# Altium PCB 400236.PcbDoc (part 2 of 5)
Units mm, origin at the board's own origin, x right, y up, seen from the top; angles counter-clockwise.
Board outline 136.53 x 63.5 mm, 4 copper layers (Top Layer, Mid-Layer 1, Mid-Layer 2, Bottom Layer), stack 1.505 mm thick; 340 components, 230 nets, 1369 pads, 1292 vias.
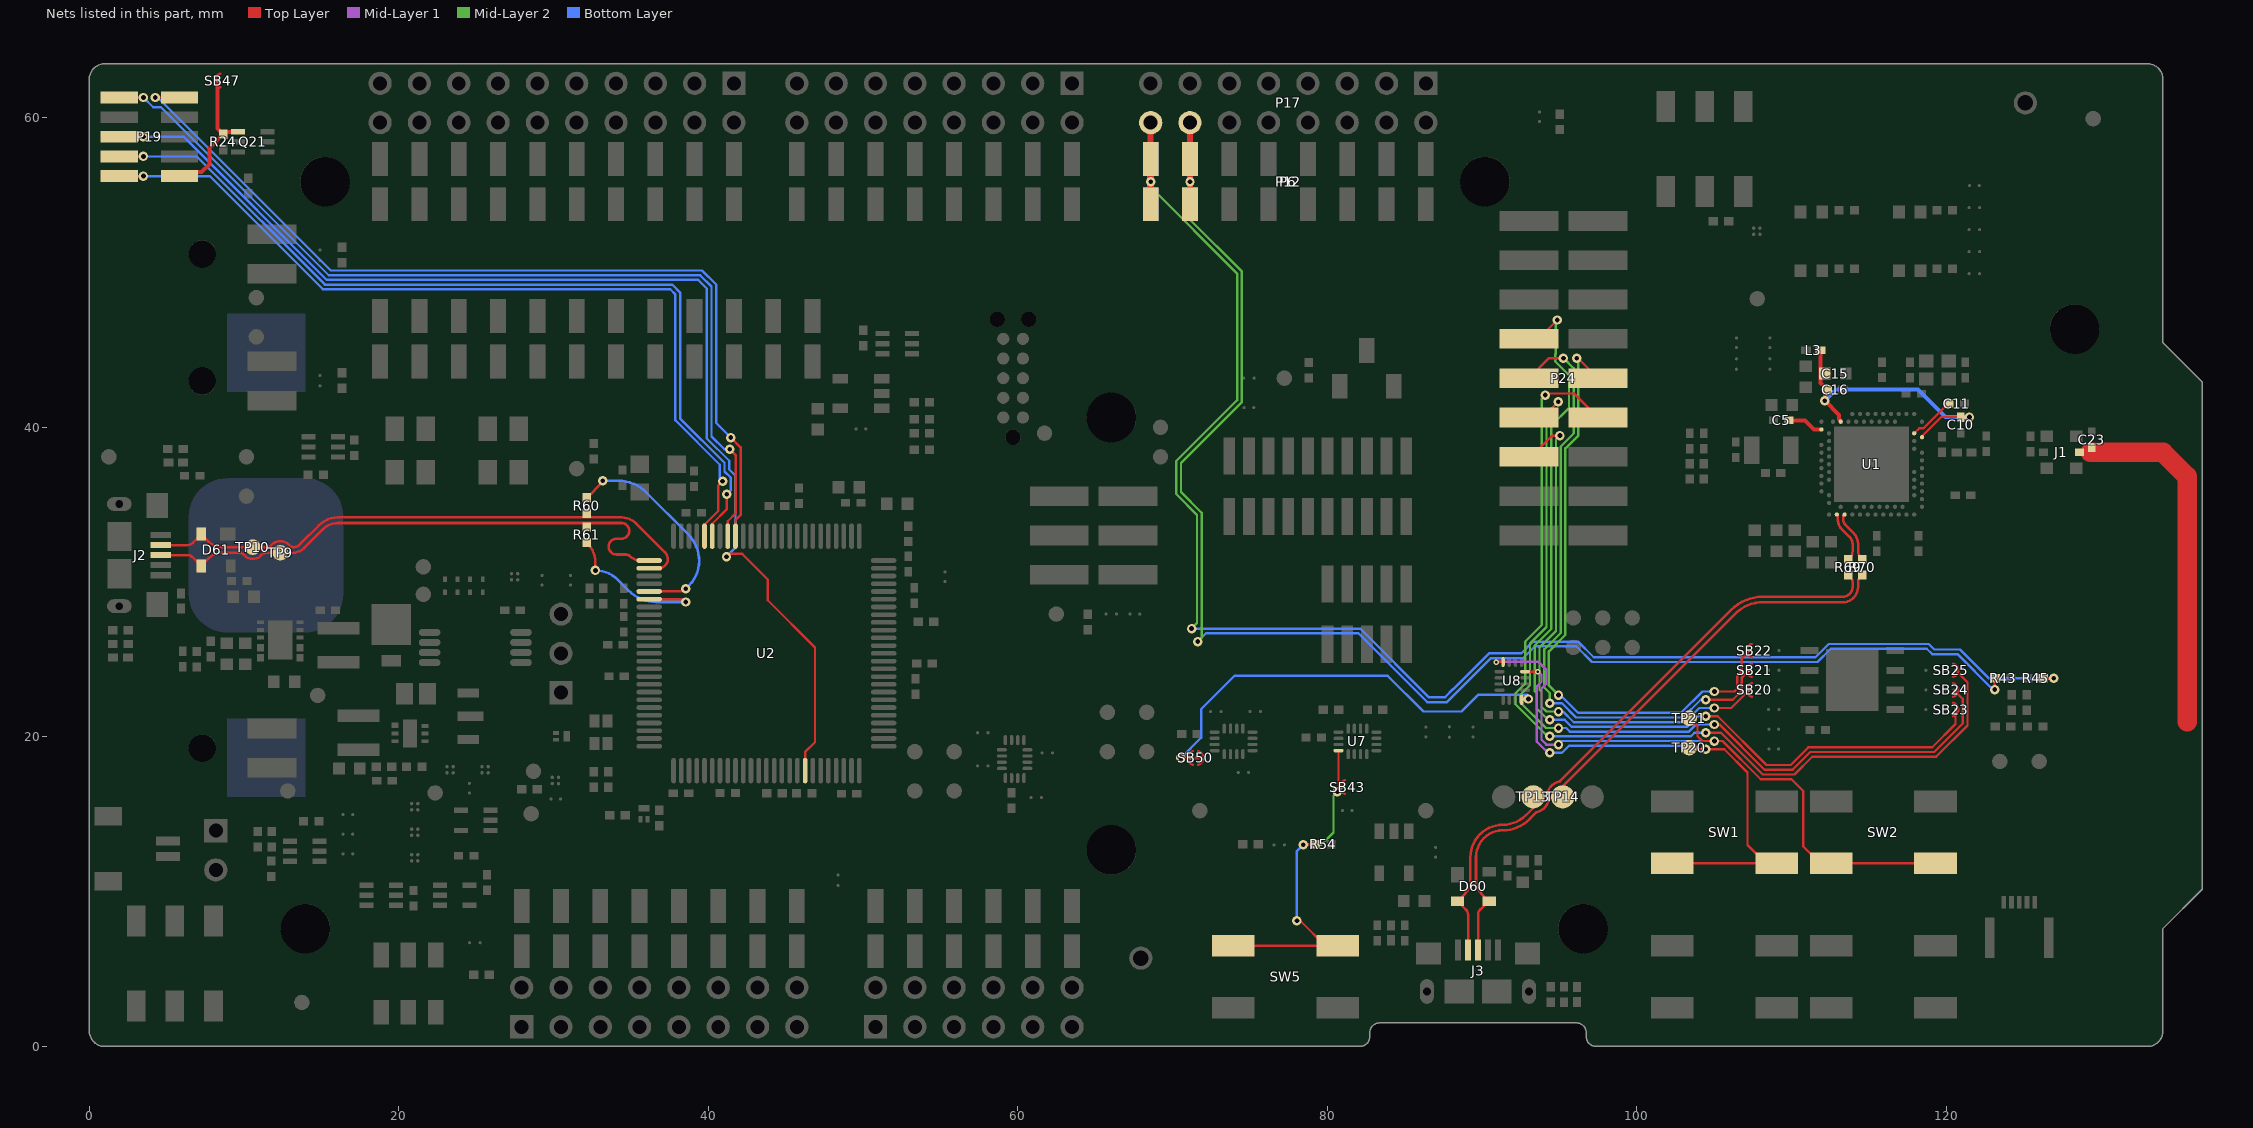
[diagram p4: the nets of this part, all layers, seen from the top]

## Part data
Bat1: library part "Bat Holder CR2032 SMD", "Bat Holder CR2032 SMD", 2nd source part number=165-0693, Manufacturer=Comfortable, Manufacturer Part Number=BC-2001, Supplier part number="BC-2001/T & R"
C1 C2 C17 C18: library part C0402-12p, "Capacitor, NP0, ±2%", Part number IPS=00000002398
C3 C4: library part C0402-1.0p, "Capacitor, NP0, ±0.1pF", Supplier part number=490-6073-1-ND
C5 C7 C8 C12 C24 C25 C26 C28 C31 C32 C33 C34 C35 C36 C37 C40 C41 C42 C43 C45 C48 C49 C50 C62 C65 C66 C67 C68 C69 C85 C89 C90 C93: library part C0402-100n, "Capacitor, X7R, ±10%", Part number IPS=00000005296
C6 C20: library part C0603-4µ7-6.3V-X7R, "Capacitor, X7R, ±10%", Manufacturer=Samsung, Manufacturer Part Number=CL10B475KQ8NQNC, Supplier part number=1276-2087-1-ND
C9: library part C0402-820p, "Capacitor, NP0, ±5%"
C10 C13 C22 C51 C52: library part C0402-N.C., "Not mounted"
C11: library part C0402-100p, "Capacitor, NP0, ±5%", Part number IPS=00000002361
C14 C15 C91 C92: library part C0603-1µ0, "Capacitor, X7R, ±10%", Part number IPS=00000000616
C16: library part C0402-47n, "Capacitor, X7R, ±10%"
C19 C21: library part C0603-4µ7-10V-X7S, "Capacitor, X7S, ±10%", Supplier part number=445-14258-1-ND
C23: library part C0402-1.2p, "Capacitor, NP0, ±0.1pF", Part number IPS=00000005410
C27: library part C0402-10p, "Capacitor, NP0, ±2%", 2nd source part number=185-6064, Supplier part number=712-1252-1-ND
C29 C30: library part C0402-18p, "Capacitor, NP0, ±5%"
C38 C39 C61 C64: library part C0603-10µ, "Capacitor, X5R, ±20%", Part number IPS=00000007785
C44 C60 C63: library part C0402-10n, "Capacitor, X7R, ±10%", Part number IPS=00000007784
C46 C47: library part C0402-300p, "Capacitor, NP0, ±5%", Supplier part number=490-3234-1-ND
C80 C82 C83 C88: library part C0603-10µF-25V, "Capacitor, 0603, 25V, X5R"
C81: library part C0402-15p, "Capacitor, NP0, ±5%", Part number IPS=00000002401
C84: library part C0402-470n, "Capacitor, X5R, ±10%"
C86: library part C0805-4µ7, "Capacitor, X5R, ±10%"
C87: library part C0402-150p, "Capacitor, NP0, ±5%", Part number IPS=00000007972
D60 D61: "Ultra low capacitance double rail-to-rail ESD protection diode", 2nd source part number=152-4157, Manufacturer=NXP, Supplier part number=568-4140-1-ND
D80 D81 D82 D83: "20V schottky barrier diode, Vf 350 mV @ 100 mA, Ir 2.0 µA @ 10 V, If 500 mA", Manufacturer="ON Semiconductor", Supplier part number=NSR0620P2T5GOSCT-ND
D84: "Diode Schottky Vf=0.455V @ 100mA, Vr=10V, If=1000mA, Ir=1µA @ 10V", 2nd source part number=236-9429, Manufacturer="ON Semiconductor", Manufacturer Part Number=MBRM110ET1G, Supplier part number=MBRM110ET1GOSTR-ND
FB60 FB61 FB62 FB63 FB64 FB65: library part FB0402-120R@100M-500mA, "Ferrite Bead, 120 Ohm @ 100MHz, 500mA, 250 mOhm Max", 2nd source part number=151-5760, Manufacturer=Murata, Manufacturer Part Number=BLM15AG121SN1D, Supplier part number=490-1005-1-ND
Fid1 Fid2: library part Fid-Mark, "Fiducial Mark"
J1: "Coaxial Connector with Switch", 2nd source part number=81-MM8130-2600RA2, Manufacturer=Murata, Supplier part number=490-4981-1-ND
J2 J3: library part USB-Micro-B-RA-SMD-PiP, "MicroUSB-B-SMT", 2nd source part number=609-4616-1-ND, Manufacturer="Allen Creations Corp.", Manufacturer Part Number=AJU55-BS2111-L, Part number IPS=00000007790
J4: library part TC2050-IDC-NLFP, "CBL PLUG-OF-NAILS 10-PIN", Manufacturer="Tag-Connect LLC", Supplier part number=TC2050-IDC-NL-ND
J5: library part FPC_05P-0.5mm-RA-SMD, "0.5mm FPC, 5P,Right Angle SMT,Double Contact,H=1.2mm,White, Tin plated", 2nd source part number=WM9836CT-ND, Manufacturer=W-CON, Manufacturer Part Number=5141-05RZDNWR01, Part number IPS=00000007792
J6: library part SM02B-SRSS-TB, "1.0mm pitch connector side entry SMD", Manufacturer=JST, Manufacturer Part Number=SM02B-SRSS-TB(LF)(SN), Part number IPS=00000007791, Supplier part number=455-1802-1-ND
L1: library part L0402-3n9, "Inductor, 170mA, ±0.1nH", Manufacturer=Murata, Manufacturer Part Number=LQP15MN3N9B02D, Part number IPS=00000007793, Supplier part number=490-1131-1-ND
L2 L4: library part L0603-10µ, "Inductor, 80mA, ±10%", 2nd source part number=178-6105, Manufacturer="Taiyo Yuden", Manufacturer Part Number=LBMF1608T100K, Part number IPS=00000007794, Supplier part number=587-1714-1-ND
L3: library part L0402-15n, "Inductor, 320mA, ±5%", 2nd source part number=658-1328, Manufacturer="Taiyo Yuden", Manufacturer Part Number=HK100515NJ-T, Part number IPS=00000003215, Supplier part number=587-1521-1-ND
L80: library part NR3015-2µ2-1.5A-72mOhm, "Ferrite Inductor, Shielded, 1,5A, 72mOhm", 2nd source part number=188-5853, Manufacturer="Taiyo Yuden", Manufacturer Part Number=NR3015T2R2M, Supplier part number=587-1648-1-ND
L81: library part NR3015-4µ7-1.04A-144mOhm, "Ferrite Inductor, Shielded, 1,04A, 144mOhm", 2nd source part number=963-NR3015T4R7M, Manufacturer="Taiyo Yuden", Manufacturer Part Number=NR3015T4R7M, Supplier part number=587-1649-1-ND
LED1 LED2 LED3 LED4: library part "VS 25C7M5", "LED, Green, 0603, 573nm, Vf=2.0V, 24mcd, - 40 to +85°C", Manufacturer="Victory Electronics"
LED5: library part LTST-C195KGJRKT, "Ultra bright AlInGaP Bi-Color LED", 2nd source part number=859-LTST-C195KGJRKT, Manufacturer="Lite-On Inc", Supplier part number=160-1452-1-ND
P1 P3 P6: library part "Socket 1x8 SMD", "Socket 1x8, 2.54mm (100mil), SMD", 2nd source part number=SSM-108-F-SV-P-TR, Manufacturer=W-CON, Manufacturer Part Number=2171-108MS0CUNR1
P2: library part "Socket 1x6 SMD", "Socket 1x6, 2.54mm (100mil), SMD", 2nd source part number=SSM-106-F-SV-P-TR, Manufacturer=W-CON, Manufacturer Part Number=2171-106MS0CUNR1
P4: library part "Socket 1x10 SMD", "Socket 1x10, 2.54mm (100mil), SMD", 2nd source part number=SSM-110-F-SV-P-TR, Manufacturer=W-CON, Manufacturer Part Number=2171-110MS0CUNR1
P5: library part "Pin Header 2x3 SMD", "Pin Header 2x3, 2.54mm (100mil) SMD", 2nd source part number=TSM-103-01-L-DV, Manufacturer=W-CON, Manufacturer Part Number=1125-1203S0M116R1
P7 P9 P12: library part "Pin List 1x8 SMD, N.C.", "Pin List 1x8, 2.54mm (100mil), SMD", 2nd source part number=TSM-108-01-L-SV-P-TR, Manufacturer=W-CON, Manufacturer Part Number=1125-1108S0M116R2
P8: library part "Pin List 1x6 SMD, N.C.", "Pin List 1x6, 2.54mm (100mil), SMD", 2nd source part number=TSM-106-01-L-SV-P-TR, Manufacturer=W-CON, Manufacturer Part Number=1125-1106S0M116R2
P10: library part "Pin List 1x10 SMD, N.C.", "Pin List 1x10, 2.54mm (100mil), SMD", 2nd source part number=TSM-110-01-L-SV-P-TR, Manufacturer=W-CON, Manufacturer Part Number=1125-1110S0M116R2
P11: library part "Socket 2x3 SMD Bottom, N.C.", "Socket 2x3, 2.54mm (100mil), SMD", 2nd source part number=SSM-103-F-DV-P-TR, Manufacturer=W-CON, Manufacturer Part Number=2171-203MS0CUNR1
P13 P15 P17: library part "Pin Header 2x8, N.C.", "Pin Header 2x8, 2.54mm (100mil)"
P14: library part "Pin Header 2x6, N.C.", "Pin Header 2x6, 2.54mm (100mil)"
P16: library part "Pin Header 2x10, N.C.", "Pin Header 2x10, 2.54mm (100mil)"
P18 P19: library part "Pin Header 2x5 SMD, 1.27mm, KS", "Pin Header 2x5, 1.27mm (50mil), SMD, Keying Shroud", 2nd source part number=FTSH-105-01-F-DV-K, Manufacturer=W-CON, Manufacturer Part Number=3132-10MS0BK00R1
P20: library part "Pin List 1x12 SMD", "Pin List 1x12, 2.54mm (100mil), SMD", Supplier part number=TSM-112-01-L-SV-P-TR
P21 P22 P23: library part "Pin List Ang 1x2 SMD, 2.54mm", "Pin List 1x2, 2.54mm (100mil), Right Angled, SMD", 2nd source part number=TSM-102-01-L-SH-A, Manufacturer=W-CON, Manufacturer Part Number=1125B-1102S0Z135R2
P24: library part "Socket 2x9 SMD", "Socket 2x9, 2.54mm (100mil), SMD", Manufacturer=Samtec, Manufacturer Part Number=SSM-109-F-DV, Supplier part number=SSM-109-F-DV-P-TR
P25: library part "Pin Header 2x10 SMD, 1.27mm, KS, N.C.", "Pin Header 2x10, 1.27mm (50mil), SMD, Keying Shroud", Manufacturer=Samtec, Manufacturer Part Number=FTSH-110-01-F-DV-K, Supplier part number=FTSH-110-01-F-DV-K-ND
P26: library part "Socket 1x12 SMD, N.C.", "Socket 1x12, 2.54mm (100mil), SMD", 2nd source part number=SSM-109-L-SV, Manufacturer=Samtec
P27: library part "Pin List 1x2, N.C.", "Pin List 1x2, 2.54mm (100mil)"
P28: library part "Pin List 1x3, N.C.", "Pin List 1x3, 2.54mm (100mil)"
Q20 Q21 Q40: "Fairchild, FDG6321C, Dual N & P Channel Digital FET", 2nd source part number=FDG6321CCT-ND, Manufacturer=Fairchild, Supplier part number=170-0689
Q80: "45V NPN high gain power transistor", Manufacturer="Diodes Incorporated", Supplier part number=FCX690BCT-ND
Q81: "Fairchild, FDG6303N, Dual N-Channel Digital FET", 2nd source part number=FDG6303NCT-ND, Manufacturer=Fairchild, Supplier part number=161-1233
Q82 Q83: "N-Channel MOSFET, 20V, 1A, 470mOhm, 400mW", 2nd source part number=755-RV2C010UNT2L, Manufacturer="Rohm Semiconductor", Supplier part number=RV2C010UNT2LCT-ND
R1 R2 R30 R44 R46 R69 R70: library part R0402-0R, "Resistor, ±5%, 0.063W", Supplier part number=146-9661, Value Ohm=0
R3 R4 R22 R23 R24 R27 R49 R62 R63: library part R0402-10k, "Resistor, ±1%, 0.063W", Part number IPS=00000002093, Supplier part number=173-8864, Value Ohm=10000
R20 R21 R47 R48 R50 R51: library part R0402-220, "Resistor, ±1%, 0.063W", Supplier part number=173-8841, Value Ohm=220
R25: library part R0402-6k8, "Resistor, ±1%, 0.063W", Supplier part number=173-8862, Value Ohm=6800
R26: library part R0402-47k, "Resistor, ±1%, 0.063W", Supplier part number=146-9719, Value Ohm=47000
R28 R29: library part R0402-150, "Resistor, ±1%, 0.063W", Supplier part number=173-8839, Value Ohm=150
R40: library part R0402-150k, "Resistor, ±1%, 0.063W", Supplier part number=165-2753, Value Ohm=150000
R41 R68 R86 R87 R89: library part R0402-1M0, "Resistor, ±1%, 0.063W", Part number IPS=00000006807, Value Ohm=1000000
R43 R45 R54 R88 R90 R91: library part R0402-N.C., "Not mounted"
R52 R53 R64 R65 R66 R67: library part R0402-4k7, "Resistor, ±1%, 0.063W", Part number IPS=00000003433, Supplier part number=173-8858, Value Ohm=4700
R60 R61: library part R0402-39R, "Resistor, ±1%, 0.063W", Part number IPS=00000000821, Supplier part number=173-8831, Value Ohm=39
R80: library part R0402-270k, "Resistor, ±1%, 0.063W", Value Ohm=270000
R81: library part R0402-30k, "Resistor, ±1%, 0.063W", Value Ohm=30000
R82: library part R0402-330k, "Resistor, ±1%, 0.063W", Value Ohm=330000
R83: library part R0402-820k, "Resistor, ±1%, 0.063W", Value Ohm=820000
R84: library part R0402-120k, "Resistor, ±1%, 0.063W", Supplier part number=169-2508, Value Ohm=120000
R85: library part R0402-470k, "Resistor, ±1%, 0.063W", Value Ohm=470000
R92 R94: library part R0402-10M, "Resistor, ±1%, 0.063W", Value Ohm=10000000
R93: library part R0402-1k0, "Resistor, ±1%, 0.063W", Part number IPS=00000002218, Supplier part number=173-8850, Value Ohm=1000
SB1 SB2 SB5 SB6 SB7 SB8 SB10 SB11 SB12 SB13 SB14 SB15 SB16 SB33 SB38 SB40 SB41 SB42 SB50 SB51 SB52 SB53 SB54 SB55 SB56 SB57 SB58 SB60 SB65: library part "Solderbridge Shorted", "Shorted Solderbridge"
SW1 SW2 SW3 SW4 SW5: library part Switch-PB-6.2x6.3mm-SMD, "Tactile Switch, SPNO, SMD, 160gf, 6.2x6.3x2.5mm", 2nd source part number=688-SKHUALE010, Manufacturer=Dailywell, Manufacturer Part Number=TS604VM1-025BR-R, Part number IPS=00000007812
SW6 SW8: "Slide Switch DPDT", Manufacturer=Dailywell
SW7: library part CJS-1200TA, "SMD slide Switch (ON-ON)", Manufacturer="Copal Electronics Inc", Supplier part number=563-1021-2-ND
SW9: "Slide Switch DP3T 300mA 6V", Manufacturer="C&K Components", Supplier part number=CKN10725CT-ND
SW10: "Slide Switch DPDT J Hook", Manufacturer="Copal Electronics Inc", Supplier part number=CAS220JTR-ND
TP1 TP2 TP3 TP4 TP5 TP6 TP7 TP8 TP9 TP10 TP11 TP12 TP17 TP18 TP19 TP20 TP21 TP22 TP23 TP24 TP25 TP26 TP27 TP28 TP29 TP30 TP31 TP32 TP33 TP34 TP35 TP36 TP37 TP38 TP39 TP42 TP43 TP44 TP45 TP46 TP47: library part TP_SMD_Ø1.0MM, "1.0mm circular SMD testpad", Manufacturer="Nordic Semiconductor"
TP13 TP14 TP15 TP16: library part TP_SMD_Ø1.5MM, "1.0mm circular SMD testpad", Manufacturer="Nordic Semiconductor"
TP40 TP41: library part "Testpoint TH", "Testpoint, through hole"
U1: library part nRF52840-QIAAC0, "Multi-protocol Bluetooth Low Energy, IEEE 802.15.4, ANT and 2.4GHz proprietary system-on-chip", Manufacturer="Nordic Semiconductor", Part number IPS=N.A.
U2: "IC MCU 32bit 128kB flash 100LQFP", 2nd source part number=184-1662, Manufacturer=Atmel, Supplier part number=ATSAM3U2CA-AU-ND
U3: library part MX25R6435FZNIL0, "Ultra low power, 64M-bit, serial multi I/O flash memory", Manufacturer=Macronix
U4 U13 U14 U15 U16 U17 U18 U24: "Semtech, 2A Low Vin, Very Low Ron, Load Switch, 4DSBGA", 2nd source part number=947-SC728CSTRT, Manufacturer="Semtech Corporation", Supplier part number=SC728CSTRTCT-ND
U5 U6 U7 U8: "Data / Audio Low-Voltage Dual DPDT Analog Switch", 2nd source part number=512-FSA2466UMX, Manufacturer="Fairchild Semiconductor", Supplier part number=FSA2466UMXCT-ND
U11: library part XC9236D08CER-G, "600mA Driver Transistor Built-In, Synchronous Step-Down DC/DC Converters", 2nd source part number=XC9236D08CER-G-ND, Manufacturer="Torex Semiconductor", Part number IPS=N.A., Supplier part number=865-XC9236D08CER-G
U12: library part XC9131H05CDR-G, "1A Driver Transistor Built-In, Multi Functional Step-Up DC/DC Converter", Manufacturer="Torex Semiconductor", Supplier part number=XC9131H05CDR-G-ND
U19: "Precision very low power CMOS dual operational amplifier", Manufacturer=STMicroelectronics, Supplier part number=497-8085-1-ND
U20 U25: library part 74LVC1G08GW, "Single 2-Input AND Gate", 2nd source part number=242-8299, Manufacturer="NXP Semiconductors", Supplier part number=568-1580-1-ND
U21: library part 74LVC1G11GW, "Single 3-input AND gate", 2nd source part number=243-8826, Manufacturer="NXP Semiconductors", Supplier part number=568-7757-1-ND
U22 U23: library part TCK106AF,LF, "1.0 A Load Switch IC with Slew Rate Control Driver in Small Package", Manufacturer=Toshiba, Part number IPS=00000007823, Supplier part number=TCK106AFLFCT-ND
X1: library part XTAL_SMD2016_32MHz_8pF_Golledge, "XTAL SMD 2016, 32MHz, Cl=8pF, Tol: ±10ppm, Stab: ±15ppm", Manufacturer=Golledge, Manufacturer Part Number=MP06003
X2: library part XTAL_SMD3215_32.768kHz_9pF_NDK, "XTAL SMD 2012, 32.768kHz, 9pF, ±20ppm", Manufacturer=NDK, Manufacturer Part Number=NX3215SA-32.768K-STD-MUA-9
X20: library part XTAL_SMD3225_12MHz_18pF_TXC, "XTAL SMD 3225, 12MHz, Cl=18pF, Tol: ±30ppm, Stab: ±30ppm", 2nd source part number=184-2056, Manufacturer="TXC Corporation", Manufacturer Part Number=7M-12.000MAAJ-T, Supplier part number=887-1121-1-ND

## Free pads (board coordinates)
  round 3.2 hole 3.2 unplated: 1(13.97,7.62) 1(15.24,55.88) 1(66.04,12.7) 1(66.04,40.64) 1(90.17,55.88) 1(96.52,7.62) 1(128.27,46.355)
  round 0.35 on Mech16: 1(112.414,36.617) 1(112.414,37.117) 1(112.414,37.617) 1(112.414,38.117) 1(112.414,38.617) 1(114.164,34.867) 1(114.164,40.367) 1(114.414,34.367) 1(114.664,34.867) 1(114.664,40.367) 1(114.914,34.367) 1(115.164,34.867) 1(115.164,40.367) 1(115.664,34.867) 1(115.664,40.367) 1(116.164,34.867) 1(116.164,40.367) 1(116.664,34.867) 1(116.664,40.367) 1(117.164,34.867) 1(117.914,35.617) 1(117.914,36.117) 1(117.914,36.617) 1(117.914,37.117)

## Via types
v1: diameter 0.61, hole 0.305, Top Layer to Bottom Layer, tented both sides, 1088 vias
v2: diameter 0.35, hole 0.15, Top Layer to Mid-Layer 1, tented both sides, 180 vias
v3: diameter 0.61, hole 0.305, Top Layer to Bottom Layer, 24 vias

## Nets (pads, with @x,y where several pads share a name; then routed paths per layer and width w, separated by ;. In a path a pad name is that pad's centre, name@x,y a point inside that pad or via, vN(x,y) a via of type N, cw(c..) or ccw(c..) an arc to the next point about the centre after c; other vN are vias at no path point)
ANT: C23.1 J1.3 | length 22.7
  Top Layer w1.27: 129.303,38.391 133.992,38.391 135.551,36.832 135.551,20.99
BOOT/RESET: R54.1 SB43.1 SW5.2 U7.16 | length 23.2
  Top Layer w0.152: SW5.2@73.917,6.502 SW5.2@80.667,6.502 ; v1(78.029,8.128) 78.241,8.128 SW5.2@79.913,6.456 ; v1(78.435,13.03) 79.18,13.03 R54.1@79.231,13.081 ; v1(80.645,16.459) 80.95,16.764 80.95,16.782 80.715,17.016 U7.16@80.715,19.11 U7.16@80.68,19.11
  Mid-Layer 2 w0.152: v1(78.435,13.03) 79.604,13.03 80.391,13.818 80.391,16.205 v1(80.645,16.459)
  Bottom Layer w0.152: v1(78.029,8.128) 78.029,12.624 v1(78.435,13.03)
BUTTON1: SW1.2 TP20.1 U8.4 | length 35.3
  Top Layer w0.152: U8.4@92.773,24.222 93.609,24.222 v2@93.624,24.206 ; SW1.2@102.278,11.83 SW1.2@108.331,11.83 ; TP20.1@103.378,19.304 103.48,19.202 v1(104.445,19.202) 105.634,19.202 107.137,17.699 107.137,13.024 SW1.2@108.331,11.83 ; SW1.2@109.707,11.83 SW1.2@109.028,11.83 SW1.2@108.331,11.83
  Mid-Layer 1 w0.152: v2@93.624,24.206 93.828,24.003 93.828,23.562 93.531,23.266 93.531,19.693 94.251,18.974 v1(94.369,18.974)
  Bottom Layer w0.152: v1(94.369,18.974) 95.149,18.974 95.606,19.431 103.454,19.431 103.683,19.202 v1(104.445,19.202)
  other v2: 93.599,24.206
BUTTON2: SW2.2 TP21.1 U8.8 | length 42.9
  Top Layer w0.152: v2@90.887,24.847 U8.8@91.348,24.847 ; TP21.1@103.378,21.234 103.914,20.699 103.914,20.049 104.227,19.736 v1(105.004,19.736) 105.532,19.736 107.995,17.272 109.981,17.272 110.744,16.509 110.744,12.927 111.841,11.83 SW2.2@112.54,11.83 SW2.2@119.29,11.83 SW2.2@119.913,11.83
  Mid-Layer 1 w0.152: v2@90.887,24.847 93.645,24.847 94.132,24.359 94.132,23.436 93.836,23.139 93.836,19.82 94.148,19.507 v1(94.928,19.507)
  Bottom Layer w0.152: v1(94.928,19.507) 95.157,19.736 v1(105.004,19.736)
  other v2: 90.912,24.822
CTS: SB50.1 U8.16 | length 28.9
  Top Layer w0.152: U8.16@92.548,22.397 v1@92.907,22.397 ; v1@93.04,22.53 v1@92.907,22.397 ; v1@93.167,22.479 93.085,22.397 v1@92.907,22.397
  Top Layer w0.203: v1(70.536,18.644) 70.963,18.644 SB50.1@71.138,18.644
  Bottom Layer w0.152: v1(70.536,18.644) 71.839,19.947 71.839,21.794 73.998,23.952 83.887,23.952 86.199,21.641 88.664,21.641 89.756,22.733 92.913,22.733 v1@93.167,22.479
  other v1: 92.989,22.454
D20: P6.7 P12.7 P17.14 R43.1 | length 99.3
  Top Layer w0.152: v1(123.114,23.063) 123.114,23.745 R43.1@123.169,23.8
  Top Layer w0.381: P6.7@71.12,54.415 v1(71.12,55.88) P6.7@71.12,57.345 P17.14@71.12,59.69
  Mid-Layer 2 w0.152: v1(71.12,55.88) 71.12,53.417 74.473,50.064 74.473,41.631 70.536,37.694 70.536,35.822 71.882,34.475 71.882,26.416 v1(71.628,26.162)
  Bottom Layer w0.152: v1(71.628,26.162) 72.161,26.695 82,26.695 86.445,22.25 87.729,22.25 90.571,25.092 92.648,25.092 93.413,25.857 96.073,25.857 97.089,24.841 111.658,24.841 ; 111.658,24.845 112.518,25.704 118.721,25.704 119.075,25.349 120.701,25.349 122.987,23.063 v1(123.114,23.063)
  Bottom Layer w0.381: P12.7@71.12,54.415 v1(71.12,55.88) P12.7@71.12,57.345
D21: P6.8 P12.8 P17.16 R45.1 | length 102.9
  Top Layer w0.152: R45.1@126.251,23.8 v1(126.928,23.8)
  Top Layer w0.381: P6.8@68.58,54.415 v1(68.58,55.88) P6.8@68.58,57.345 P17.16@68.58,59.69
  Mid-Layer 2 w0.152: v1(68.58,55.88) 68.58,55.526 74.168,49.938 74.168,41.758 70.231,37.821 70.231,35.695 71.577,34.349 71.577,27.356 v1(71.222,27)
  Bottom Layer w0.152: v1@71.425,27 82.126,27 86.571,22.555 87.603,22.555 87.63,22.582 87.63,22.598 88.121,23.089 88.137,23.089 90.445,25.397 92.521,25.397 93.287,26.162 96.196,26.162 97.212,25.146 111.532,25.146 112.392,26.006 118.849,26.006 119.201,25.654 120.861,25.654 122.715,23.8 v1(126.928,23.8)
  Bottom Layer w0.381: P12.8@68.58,54.415 v1(68.58,55.88) P12.8@68.58,57.345
D28: P24.7 SB23.2 | length 60
  Top Layer w0.152: P24.7@93.027,45.72 93.624,45.72 v1(94.844,46.939) ; v1(104.445,21.336) 105.225,21.336 108.374,18.186 109.932,18.186 111.075,19.329 119.076,19.329 120.581,20.835 SB23.2@120.581,21.768
  Mid-Layer 2 w0.152: v1(94.369,21.107) 94.251,21.107 93.531,21.827 93.531,22.811 93.396,22.947 93.396,25.909 94.463,26.976 94.463,40.107 95.606,41.25 95.606,43.365 94.717,44.254 94.717,44.722 94.742,44.747 94.742,46.838 v1(94.844,46.939)
  Bottom Layer w0.152: v1(94.369,21.107) 95.327,21.107 95.784,20.65 103.231,20.65 103.917,21.336 v1(104.445,21.336)
D30: P24.9 SB21.2 | length 41.3
  Top Layer w0.152: P24.9@93.027,43.18 94.323,44.475 v1(95.25,44.475) ; v1(104.445,22.403) 106.191,22.403 106.78,22.992 106.78,23.831 107.108,24.159 SB21.2@107.257,24.308
  Mid-Layer 2 w0.152: v1(94.369,22.174) 94.369,22.835 94.005,23.199 94.005,25.656 95.072,26.723 95.072,38.768 95.91,39.606 95.91,43.815 v1(95.25,44.475)
  Bottom Layer w0.152: v1(94.369,22.174) 95.149,22.174 96.064,21.26 102.979,21.26 104.122,22.403 v1(104.445,22.403)
D31: P24.10 SB22.2 | length 40.2
  Top Layer w0.152: v1(96.114,44.475) 96.177,44.475 P24.10@97.472,43.18 ; v1(105.004,22.936) 106.293,22.936 106.475,23.118 106.475,23.957 106.78,24.262 106.78,25.101 107.108,25.429 SB22.2@107.257,25.578
  Mid-Layer 2 w0.152: v1(94.928,22.708) 94.31,23.326 94.31,25.53 95.377,26.597 95.377,38.642 96.215,39.48 96.215,44.374 v1(96.114,44.475)
  Bottom Layer w0.152: v1(94.928,22.708) 95.047,22.708 96.19,21.565 102.852,21.565 104.224,22.936 v1(105.004,22.936)
D32: P24.11 SB24.2 | length 57.2
  Top Layer w0.152: P24.11@93.027,40.64 93.904,40.64 v1(94.92,41.656) ; v1(105.004,20.803) 105.327,20.803 108.248,17.882 110.058,17.882 111.201,19.025 119.202,19.025 121.049,20.872 121.049,22.461 120.472,23.038
  Mid-Layer 2 w0.152: v1(94.92,41.656) 94.158,40.894 94.158,27.102 93.091,26.035 93.091,23.335 92.456,22.7 92.456,22.233 94.115,20.574 v1(94.928,20.574)
  Bottom Layer w0.152: v1(94.928,20.574) 95.429,20.574 95.658,20.345 103.357,20.345 103.814,20.803 v1(105.004,20.803)
D33: P24.12 SB25.2 | length 61.3
  Top Layer w0.152: v1(94.082,42.088) 94.183,42.189 95.923,42.189 P24.12@97.472,40.64 ; v1(104.445,20.269) 105.429,20.269 108.122,17.577 110.184,17.577 111.327,18.72 119.329,18.72 121.354,20.745 121.354,23.535 SB25.2@120.581,24.308
  Mid-Layer 2 w0.152: v1(94.082,42.088) 93.853,41.859 93.853,27.229 92.786,26.162 92.786,23.461 92.151,22.826 92.151,22.106 94.217,20.041 v1(94.369,20.041)
  Bottom Layer w0.152: v1(94.369,20.041) 103.484,20.041 103.712,20.269 v1(104.445,20.269)
D34: P24.13 SB20.2 | length 35.3
  Top Layer w0.152: P24.13@93.091,38.036 94.526,39.472 v1(95.021,39.472) ; v1(105.004,21.869) 106.088,21.869 107.108,22.889 SB20.2@107.257,23.038
  Mid-Layer 2 w0.152: v1(94.928,21.641) 94.148,21.641 93.836,21.953 93.836,22.938 93.701,23.073 93.701,25.782 94.767,26.849 94.767,39.218 v1(95.021,39.472)
  Bottom Layer w0.152: v1(94.928,21.641) 95.225,21.641 95.91,20.955 103.105,20.955 104.019,21.869 v1(105.004,21.869)
D*_N: D60.2 J3.2 R69.2 TP13.1 | length 39.8
  Top Layer w0.165: J3.2@89.086,5.985 89.086,8.495 ccw(c88.578,8.495) 88.938,8.855 D60.2@88.402,9.39 88.912,9.899 ccw(c88.114,10.697) 89.242,10.697 89.242,12.23 cw(c91.338,12.23) 91.338,14.326 ccw(c91.338,16.411) 92.813,14.936 94.183,16.307 ; 94.204,16.333 cw(c95.199,16.129) 94.995,17.124 ; 94.998,17.121 106.088,28.211 cw(c108.136,26.162) 108.136,29.06 113.295,29.06 ccw(c113.295,29.693) 113.928,29.693 113.928,30.023 ccw(c113.548,30.023) 113.817,30.291 R69.2@113.65,30.458
D*_P: D60.3 J3.3 R70.2 TP14.1 | length 39.9
  Top Layer w0.165: J3.3@89.734,5.983 89.734,8.495 cw(c90.242,8.495) 89.883,8.855 ; 89.883,8.854 D60.3@90.429,9.4 ; D60.3@90.44,9.39 89.931,9.899 cw(c90.729,10.697) 89.6,10.697 89.6,12.232 cw(c91.338,12.232) 91.338,13.97 ccw(c91.338,16.418) 93.069,14.687 93.522,15.139 ccw(c93.294,16.129) 94.284,15.901 ; 94.284,15.902 106.34,27.958 cw(c108.136,26.162) 108.136,28.702 113.295,28.702 ; 113.295,28.702 ccw(c113.295,29.693) 114.286,29.693 114.286,30.023 cw(c114.666,30.023) 114.397,30.291 R70.2@114.565,30.458
D_N: R69.1 U1.AD4 | length 3.4
  Top Layer w0.165: U1.AD4@112.914,34.367 112.982,34.299 112.982,34.061 ; 112.977,34.061 ccw(c113.89,34.061) 113.244,33.415 113.741,32.918 cw(c113.29,32.467) 113.928,32.467 113.928,32.004 cw(c113.282,32.004) 113.739,31.547 R69.1@113.65,31.458
D_P: R70.1 U1.AD6 | length 3.4
  Top Layer w0.165: U1.AD6@113.414,34.367 113.335,34.289 113.335,34.061 ccw(c113.89,34.061) 113.498,33.669 113.994,33.172 cw(c113.29,32.467) 114.286,32.467 114.286,32.004 ccw(c114.933,32.004) 114.476,31.547 R70.1@114.565,31.458
DEC1: C5.1 U1.C1 | length 2.3
  Top Layer w0.25: C5.1@109.824,40.455 110.851,40.455 111.439,39.867 U1.C1@111.914,39.867
DEC3: C11.1 U1.D23 | length 3
  Top Layer w0.152: U1.D23@117.914,39.617 117.919,39.617 118.244,39.942 118.514,39.942 120.114,41.542 C11.1@120.164,41.542
DEC4_6: C10.2 C15.2 C16.1 L3.1 U1.B5 U1.E24 | length 19.2
  Top Layer w0.15: U1.E24@118.414,39.367 118.414,39.423 119.657,40.667 v1(121.478,40.667)
  Top Layer w0.25: L3.1@111.864,44.992 111.864,42.867 112.139,42.592 v1(112.139,41.729) 113.064,40.805 113.064,40.544 113.164,40.444 U1.B5@113.164,40.367
  Bottom Layer w0.25: v1(112.139,41.729) 112.852,42.443 118.161,42.443 119.937,40.667 v1(121.478,40.667)
DFSD_N: R60.1 U2.80 | length 14.7
  Top Layer w0.165: R60.1@32.157,35.449 v1@33.138,36.43 ; v1@33.138,36.43 ccw(c33.017,36.551) v1(33.188,36.551) ; U2.80@36.179,29.403 38.065,29.403 ; 38.108,29.403 ccw(c38.108,30.023) v1@38.547,29.584
  Bottom Layer w0.165: v1(33.188,36.551) 34.193,36.551 cw(c34.193,34.011) 35.989,35.807 38.692,33.103 cw(c36.958,31.369) 39.411,31.369 cw(c37.181,31.369) 38.758,29.792 v1(38.547,29.582)
DFSD_P: R61.1 U2.81 | length 10.9
  Top Layer w0.165: R61.1@32.148,32.572 R61.1@32.157,32.581 ; R61.1@32.157,32.563 cw(c30.833,31.239) 32.705,31.239 v1(32.705,30.759) ; U2.81@36.179,28.9 38.09,28.9 ; 38.108,28.9 cw(c38.108,28.279) v1@38.547,28.718
  Bottom Layer w0.165: v1(32.705,30.759) cw(c32.705,28.736) 34.136,30.167 34.841,29.462 ccw(c36.637,31.258) 36.637,28.718 v1@38.547,28.718
  other v1: 38.547,28.721
DHSD_N: D61.2 J2.2 R60.2 TP10.1 U2.77 | length 38.5
  Top Layer w0.165: J2.2@4.619,32.398 6.34,32.398 ccw(c6.34,32.906) 6.699,32.546 D61.2@7.234,33.082 ; D61.2@7.244,33.105 cw(c7.211,33.105) D61.2@7.235,33.082 ; 13.153,32.259 ccw(c13.153,32.935) 13.631,32.457 14.84,33.666 ; 13.183,32.259 cw(c13.183,32.568) 12.964,32.349 12.88,32.433 ccw(c12.344,31.897) 12.344,32.655 ccw(c12.344,31.901) 11.811,32.434 11.727,32.35 cw(c11.506,32.571) 11.506,32.259 8.552,32.259 cw(c8.552,33.388) 7.754,32.59 7.244,33.099 D61.2@7.244,33.105 cw(c7.211,33.105) D61.2@7.234,33.082 ; 14.837,33.669 cw(c16.073,32.433) 16.073,34.181 ; 16.063,34.181 34.407,34.181 cw(c34.407,32.876) 35.33,33.799 37.203,31.926 ; U2.77@36.179,30.9 U2.77@36.774,30.9 ; 37.203,31.926 cw(c36.774,31.497) 36.774,30.891 ccw(c36.774,31.497) 37.203,31.926
DHSD_P: D61.3 J2.3 R61.2 TP9.1 U2.76 | length 37.9
  Top Layer w0.165: J2.3@4.619,31.75 6.34,31.75 cw(c6.34,31.242) 6.699,31.601 D61.3@7.244,31.055 7.244,31.062 7.754,31.571 ; 15.102,33.425 cw(c16.063,32.464) 16.063,33.823 34.407,33.823 ; 15.112,33.435 13.884,32.207 cw(c13.147,32.944) 13.147,31.901 11.405,31.901 ccw(c11.405,31.589) 11.184,31.81 11.1,31.726 cw(c10.566,32.259) 10.566,31.505 cw(c10.566,32.263) 10.031,31.727 9.947,31.811 ccw(c9.728,31.592) 9.728,31.901 8.551,31.901 ; 34.072,31.788 cw(c34.072,32.296) 34.072,32.804 ; 34.077,31.788 34.68,31.788 cw(c34.68,31.441) 34.925,31.686 ccw(c35.617,32.378) 35.617,31.4 U2.76@36.179,31.4 ; 34.082,32.804 34.382,32.804 ccw(c34.382,33.312) 34.382,33.82 ; 7.754,31.571 cw(c8.551,30.773) 8.551,31.901 ; 7.754,31.571 cw(c8.551,30.773) 8.551,31.901
EXT_GND_DETECT: P19.9 U2.67 | length 59.9
  Top Layer w0.152: v1(4.267,61.316) P19.9@5.836,61.316 ; v1(41.453,39.345) 42.088,38.71 42.088,37.897 42.088,37.236 42.088,37.084 42.088,34.344 41.754,34.011 U2.67@41.754,32.975
  Bottom Layer w0.152: v1(4.267,61.316) 4.427,61.316 15.603,50.14 39.597,50.14 40.513,49.224 40.513,40.284 v1(41.453,39.345)
EXT_RESET: P19.10 U2.68 | length 60.5
  Top Layer w0.152: P19.10@1.936,61.316 v1(3.505,61.316) ; U2.68@41.25,32.98 U2.68@41.254,32.975 41.254,33.833 41.254,33.942 41.783,34.47 41.783,38.176 v1(41.377,38.583)
  Bottom Layer w0.152: v1(3.505,61.316) 4.14,60.681 4.631,60.681 15.477,49.835 39.471,49.835 40.208,49.097 40.208,39.413 41.039,38.583 v1(41.377,38.583)
EXT_SWDCLK: P19.4 U2.70 | length 57.5
  Top Layer w0.152: P19.4@1.936,57.506 v1(3.505,57.506) ; U2.70@40.254,32.975 40.254,33.778 41.199,34.723 v1(41.199,35.687)
  Bottom Layer w0.152: v1(3.505,57.506) 6.944,57.506 15.224,49.225 37.667,49.225 38.176,48.716 38.176,40.583 41.046,37.713 41.046,37.16 41.453,36.754 41.453,35.941 v1(41.199,35.687)
EXT_SWDIO: P19.2 U2.71 | length 56.5
  Top Layer w0.152: P19.2@1.936,56.236 v1(3.505,56.236) ; U2.71@39.754,32.975 39.754,33.709 40.64,34.595 40.64,36.246 v1(40.919,36.525)
  Bottom Layer w0.152: v1(3.505,56.236) 7.783,56.236 15.098,48.92 37.541,48.92 37.871,48.59 37.871,40.457 40.742,37.587 40.742,36.703 v1(40.919,36.525)
EXT_SWO: P19.6 U2.18 | length 77.7
  Top Layer w0.152: P19.6@1.936,58.776 v1(3.505,58.776) ; v1(41.173,31.648) 41.351,31.826 42.189,31.826 43.84,30.175 43.84,28.829 46.888,25.781 46.888,19.66 46.254,19.025 U2.18@46.254,17.825
  Bottom Layer w0.152: v1(3.505,58.776) 6.108,58.776 6.407,58.477 ; 6.405,58.475 15.351,49.53 39.345,49.53 39.903,48.971 39.903,39.287 41.351,37.839 41.351,37.286 41.758,36.88 41.758,32.233 v1(41.173,31.648)
EXT_VTG: P19.1 Q21.4 R24.1 SB47.2 | length 8.9
  Top Layer w0.254: P19.1@5.836,56.49 7.264,56.49 7.772,56.998 7.772,58.056 R24.1@8.661,58.945 8.298,59.309 8.298,62.055 SB47.2@8.298,62.408 ; R24.1@8.811,59.095 Q21.4@9.616,59.095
